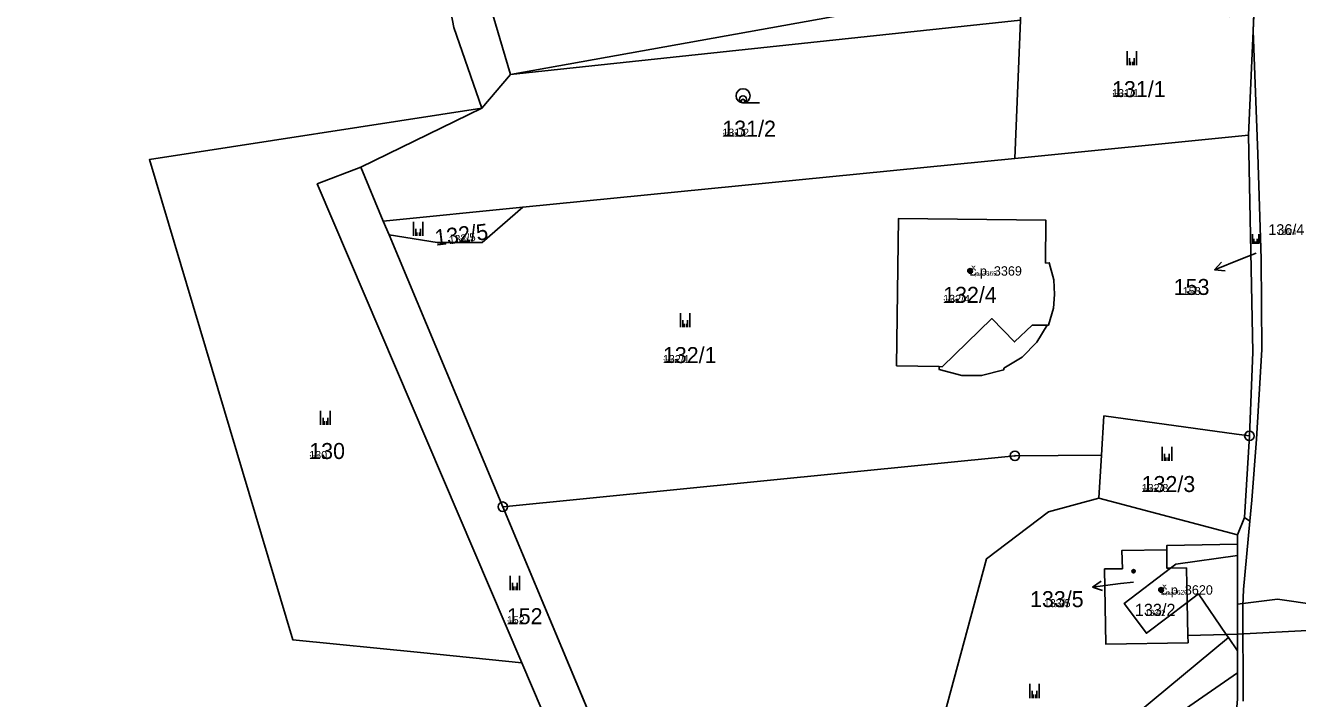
# Model space of a CAD drawing. Extents: x -759873 to -758487, y -975024 to -973516.
# Drawn here: x -759433 to -759297.9, y -974475 to -974403.4 of the extents above; entities that cross this region are included whole.
import ezdxf

# ---------------------------------------------------------------- set-up
doc = ezdxf.new("R2010")
doc.units = 0
for name, color, linetype in [('KAT_02_hranice parcel', 7, 'Continuous'), ('KAT_03_1000_st čísla parcelní', 7, 'Continuous'), ('KAT_03_1000_čísla parcelní', 7, 'Continuous'), ('KAT_03_1000_čísla popisná', 7, 'Continuous'), ('KAT_03_250_st čísla parcelní', 7, 'Continuous'), ('KAT_03_250_čísla parcelní', 7, 'Continuous'), ('KAT_03_250_čísla popisná', 7, 'Continuous'), ('KAT_03_500_st čísla parcelní', 7, 'Continuous'), ('KAT_03_500_čísla parcelní', 7, 'Continuous'), ('KAT_03_500_čísla popisná', 7, 'Continuous'), ('KAT_04_vnitřní kresba', 7, 'Continuous'), ('KAT_05_1000_značky kultur', 7, 'Continuous'), ('KAT_05_250_značky kultur', 7, 'Continuous'), ('KAT_05_500_značky kultur', 7, 'Continuous'), ('KAT_07_1000_značky budov', 7, 'Continuous'), ('KAT_07_250_značky budov', 7, 'Continuous'), ('KAT_07_500_značky budov', 7, 'Continuous'), ('KAT_10_věcná břemena', 7, 'Continuous'), ('KAT_11_značky bodu BP', 7, 'Continuous'), ('KAT_12_pomocná šipka', 7, 'Continuous'), ('KAT_14_plocha_budovy', 7, 'Continuous'), ('KAT_14_plocha_pozemek', 7, 'Continuous')]:
    doc.layers.add(name, color=color, linetype=linetype)

msp = doc.modelspace()

# ---------------------------------------------------------------- linework, layer by layer
at = {"layer": 'KAT_02_hranice parcel'}
for p, q in [((-759302.67, -974403.97), (-759302.28, -974395.1)), ((-759303.15, -974415.06), (-759302.67, -974403.97)), ((-759397.43, -974418.48), (-759384.57, -974412.22)), ((-759327.97, -974417.54), (-759303.15, -974415.06)), ((-759380.23, -974422.73), (-759327.97, -974417.54)), ((-759397.43, -974418.48), (-759395.04, -974424.2)), ((-759395.04, -974424.2), (-759380.23, -974422.73)), ((-759394.43, -974425.67), (-759395.04, -974424.2)), ((-759394.43, -974425.67), (-759382.35, -974454.57)), ((-759303.57, -974455.73), (-759303.06, -974447.05)), ((-759319.06, -974453.68), (-759318.77, -974449.1)), ((-759319.06, -974453.68), (-759304.32, -974457.57)), ((-759382.35, -974454.57), (-759357.95, -974512.98)), ((-759304.32, -974457.57), (-759303.57, -974455.73)), ((-759304.32, -974458.57), (-759304.32, -974457.57)), ((-759304.32, -974458.57), (-759304.32, -974459.77)), ((-759305.51, -974468.16), (-759305.29, -974468.48)), ((-759304.33, -974469.88), (-759305.29, -974468.48)), ((-759304.32, -974472.23), (-759304.33, -974469.88)), ((-759304.33, -974475.03), (-759304.32, -974472.23))]:
    msp.add_line(p, q, dxfattribs=at)
for points in [[(-759387.93, -974386.9), (-759390.61, -974387.43), (-759387.55, -974403.62), (-759384.57, -974412.22)], [(-759384.57, -974412.22), (-759381.52, -974408.61), (-759327.22, -974398.86)], [(-759327.22, -974398.86), (-759327.38, -974402.84), (-759327.97, -974417.54)], [(-759303.57, -974455.73), (-759303.02, -974456.1), (-759302.81, -974453.88), (-759302.31, -974447.39), (-759301.72, -974437.86), (-759301.82, -974428.21), (-759302.16, -974417.11), (-759302.67, -974403.97)], [(-759384.57, -974412.22), (-759419.87, -974417.67), (-759404.65, -974468.71), (-759391.07, -974470.08), (-759380.34, -974471.16)], [(-759303.06, -974447.05), (-759302.68, -974438.14), (-759303.15, -974415.06)], [(-759380.34, -974471.16), (-759402.05, -974420.26), (-759397.43, -974418.48)], [(-759380.23, -974422.73), (-759384.54, -974426.48), (-759389.3, -974426.48), (-759394.43, -974425.67)], [(-759323.74, -974432), (-759323.86, -974433.48), (-759324.38, -974435.26), (-759324.55, -974435.26), (-759325.63, -974437.07), (-759327.19, -974438.69), (-759329.14, -974439.85), (-759329.14, -974440.03), (-759331.5, -974440.64), (-759333.61, -974440.62), (-759335.99, -974439.99), (-759336.02, -974439.68), (-759340.53, -974439.58), (-759340.31, -974423.92), (-759324.67, -974424.12), (-759324.7, -974428.67), (-759324.32, -974428.64), (-759323.81, -974430.46), (-759323.74, -974432)], [(-759318.77, -974449.1), (-759318.5, -974444.92), (-759304.42, -974446.86), (-759303.06, -974447.05)], [(-759382.35, -974454.57), (-759327.96, -974449.16), (-759318.77, -974449.1)], [(-759336.77, -974481.63), (-759330.97, -974460.1), (-759324.39, -974455.12), (-759319.06, -974453.68)], [(-759305.51, -974468.16), (-759309.59, -974468.25), (-759309.57, -974469.03), (-759318.32, -974469.18), (-759318.44, -974461.19), (-759316.55, -974461.17), (-759316.6, -974459.22), (-759311.84, -974459.15), (-759311.84, -974458.71), (-759304.32, -974458.57)], [(-759304.32, -974459.77), (-759310.86, -974460.68), (-759311.42, -974461.1), (-759316.34, -974464.86), (-759314, -974468.02), (-759309.67, -974464.75), (-759308.47, -974463.85), (-759305.51, -974468.16)], [(-759304.33, -974469.88), (-759304.33, -974468.13), (-759304.32, -974459.77)], [(-759305.29, -974468.48), (-759324.8, -974484.72), (-759336.77, -974481.63)], [(-759380.34, -974471.16), (-759364.28, -974508.82), (-759352.33, -974538.42), (-759351.8, -974547.79)], [(-759317.94, -974495.22), (-759325.13, -974486.64), (-759304.32, -974472.23)]]:
    msp.add_lwpolyline(points, dxfattribs=at)
at = {"layer": 'KAT_03_1000_čísla popisná'}
for centre in [(-759332.72, -974429.51), (-759312.44, -974463.42)]:
    msp.add_circle(centre, 0.25, dxfattribs=at)
at = {"layer": 'KAT_03_250_čísla popisná'}
for centre in [(-759332.72, -974429.51), (-759312.44, -974463.42)]:
    msp.add_circle(centre, 0.0625, dxfattribs=at)
at = {"layer": 'KAT_03_500_čísla popisná'}
for centre in [(-759332.72, -974429.51), (-759312.44, -974463.42)]:
    msp.add_circle(centre, 0.125, dxfattribs=at)
at = {"layer": 'KAT_04_vnitřní kresba'}
for p, q in [((-759387.93, -974386.9), (-759381.52, -974408.61)), ((-759381.52, -974408.61), (-759327.38, -974402.84)), ((-759335.69, -974439.69), (-759330.4, -974434.57)), ((-759330.4, -974434.57), (-759327.99, -974437.06)), ((-759327.99, -974437.06), (-759326.12, -974435.27)), ((-759326.12, -974435.27), (-759324.55, -974435.26)), ((-759336.02, -974439.68), (-759335.69, -974439.69)), ((-759303.69, -974463.38), (-759303.02, -974456.1)), ((-759311.84, -974459.15), (-759311.82, -974461.11)), ((-759311.82, -974461.11), (-759311.42, -974461.1)), ((-759311.42, -974461.1), (-759309.75, -974461.08)), ((-759309.75, -974461.08), (-759309.67, -974464.75)), ((-759303.76, -974465.1), (-759303.69, -974463.38)), ((-759309.67, -974464.75), (-759309.59, -974468.25)), ((-759303.76, -974465.1), (-759303.71, -974475.23)), ((-759305.51, -974468.16), (-759304.33, -974468.13))]:
    msp.add_line(p, q, dxfattribs=at)
at = {"layer": 'KAT_05_1000_značky kultur'}
for p, q in [((-759316.05, -974407.63), (-759316.05, -974406.13)), ((-759315.05, -974407.63), (-759315.05, -974406.13)), ((-759356.83, -974411.64), (-759355.08, -974411.64)), ((-759391.84, -974425.79), (-759391.84, -974424.29)), ((-759390.84, -974425.79), (-759390.84, -974424.29)), ((-759302.74, -974426.61), (-759302.74, -974425.6)), ((-759302.07, -974426.61), (-759302.07, -974425.6)), ((-759363.48, -974435.5), (-759363.48, -974434)), ((-759362.48, -974435.5), (-759362.48, -974434)), ((-759401.69, -974445.87), (-759401.69, -974444.37)), ((-759400.69, -974445.87), (-759400.69, -974444.37)), ((-759312.31, -974449.7), (-759312.31, -974448.2)), ((-759311.31, -974449.7), (-759311.31, -974448.2)), ((-759381.57, -974463.43), (-759381.57, -974461.93)), ((-759380.57, -974463.43), (-759380.57, -974461.93)), ((-759326.38, -974474.91), (-759326.38, -974473.41)), ((-759325.38, -974474.91), (-759325.38, -974473.41))]:
    msp.add_line(p, q, dxfattribs=at)
msp.add_circle((-759356.83, -974410.89), 0.75, dxfattribs=at)
at = {"layer": 'KAT_05_250_značky kultur'}
for p, q in [((-759315.67, -974407.63), (-759315.67, -974407.26)), ((-759315.42, -974407.63), (-759315.42, -974407.26)), ((-759356.84, -974411.64), (-759356.4, -974411.64)), ((-759391.46, -974425.79), (-759391.46, -974425.42)), ((-759391.21, -974425.79), (-759391.21, -974425.42)), ((-759302.49, -974426.61), (-759302.49, -974426.36)), ((-759302.32, -974426.61), (-759302.32, -974426.36)), ((-759363.1, -974435.5), (-759363.1, -974435.12)), ((-759362.85, -974435.5), (-759362.85, -974435.12)), ((-759401.31, -974445.87), (-759401.31, -974445.49)), ((-759401.06, -974445.87), (-759401.06, -974445.49)), ((-759311.93, -974449.7), (-759311.93, -974449.33)), ((-759311.68, -974449.7), (-759311.68, -974449.33)), ((-759381.19, -974463.43), (-759381.19, -974463.06)), ((-759380.94, -974463.43), (-759380.94, -974463.06)), ((-759326, -974474.91), (-759326, -974474.54)), ((-759325.75, -974474.91), (-759325.75, -974474.54))]:
    msp.add_line(p, q, dxfattribs=at)
msp.add_circle((-759356.84, -974411.45), 0.187, dxfattribs=at)
at = {"layer": 'KAT_05_500_značky kultur'}
for p, q in [((-759315.8, -974407.63), (-759315.8, -974406.88)), ((-759315.3, -974407.63), (-759315.3, -974406.88)), ((-759356.84, -974411.64), (-759355.96, -974411.64)), ((-759391.59, -974425.79), (-759391.59, -974425.04)), ((-759391.08, -974425.79), (-759391.08, -974425.04)), ((-759302.57, -974426.61), (-759302.57, -974426.11)), ((-759302.24, -974426.61), (-759302.24, -974426.11)), ((-759363.23, -974435.5), (-759363.23, -974434.75)), ((-759362.72, -974435.5), (-759362.72, -974434.75)), ((-759401.44, -974445.87), (-759401.44, -974445.12)), ((-759400.94, -974445.87), (-759400.94, -974445.12)), ((-759312.06, -974449.7), (-759312.06, -974448.95)), ((-759311.56, -974449.7), (-759311.56, -974448.95)), ((-759381.32, -974463.43), (-759381.32, -974462.68)), ((-759380.82, -974463.43), (-759380.82, -974462.68)), ((-759326.13, -974474.91), (-759326.13, -974474.16)), ((-759325.62, -974474.91), (-759325.62, -974474.16))]:
    msp.add_line(p, q, dxfattribs=at)
msp.add_circle((-759356.84, -974411.26), 0.375, dxfattribs=at)
at = {"layer": 'KAT_07_1000_značky budov'}
for centre in [(-759332.73, -974429.51), (-759315.36, -974461.43), (-759312.45, -974463.42)]:
    msp.add_circle(centre, 0.175, dxfattribs=at)
at = {"layer": 'KAT_07_250_značky budov'}
for centre in [(-759332.72, -974429.51), (-759315.35, -974461.43), (-759312.44, -974463.42)]:
    msp.add_circle(centre, 0.0437, dxfattribs=at)
at = {"layer": 'KAT_07_500_značky budov'}
for centre in [(-759332.72, -974429.51), (-759315.35, -974461.43), (-759312.44, -974463.42)]:
    msp.add_circle(centre, 0.0875, dxfattribs=at)
at = {"layer": 'KAT_10_věcná břemena'}
msp.add_lwpolyline([(-759304.33, -974464.94), (-759304.33, -974468.13), (-759296.23, -974467.68), (-759296.02, -974466.22), (-759295.88, -974464.99), (-759300.06, -974464.4)], close=True, dxfattribs=at)
at = {"layer": 'KAT_11_značky bodu BP'}
for centre, radius in [((-759303.06, -974447.05), 0.5), ((-759303.06, -974447.05), 0.0303), ((-759327.96, -974449.16), 0.5), ((-759327.96, -974449.16), 0.0303), ((-759382.35, -974454.57), 0.5), ((-759382.35, -974454.57), 0.0303)]:
    msp.add_circle(centre, radius, dxfattribs=at)
at = {"layer": 'KAT_12_pomocná šipka'}
for p, q in [((-759303.97, -974428.27), (-759306.75, -974429.39)), ((-759306.75, -974429.39), (-759306.01, -974428.56)), ((-759302.34, -974427.61), (-759303.97, -974428.27)), ((-759306.75, -974429.39), (-759305.64, -974429.48)), ((-759319.72, -974463.12), (-759318.79, -974462.5)), ((-759316.74, -974462.75), (-759319.72, -974463.12)), ((-759319.72, -974463.12), (-759318.66, -974463.49)), ((-759315.35, -974462.59), (-759316.74, -974462.75))]:
    msp.add_line(p, q, dxfattribs=at)
at = {"layer": 'KAT_14_plocha_budovy'}
for points in [[(-759340.53, -974439.58), (-759336.02, -974439.68), (-759335.69, -974439.69), (-759330.4, -974434.57), (-759327.99, -974437.06), (-759326.12, -974435.27), (-759324.55, -974435.26), (-759324.38, -974435.26), (-759323.86, -974433.48), (-759323.74, -974432), (-759323.81, -974430.46), (-759324.32, -974428.64), (-759324.7, -974428.67), (-759324.67, -974424.12), (-759340.31, -974423.92)], [(-759316.6, -974459.22), (-759316.55, -974461.17), (-759318.44, -974461.19), (-759318.32, -974469.18), (-759309.57, -974469.03), (-759309.59, -974468.25), (-759309.67, -974464.75), (-759309.75, -974461.08), (-759311.42, -974461.1), (-759311.82, -974461.11), (-759311.84, -974459.15)]]:
    msp.add_lwpolyline(points, close=True, dxfattribs=at)
at = {"layer": 'KAT_14_plocha_pozemek'}
for points in [[(-759364.28, -974508.82), (-759380.34, -974471.16), (-759391.07, -974470.08), (-759404.65, -974468.71), (-759419.87, -974417.67), (-759384.57, -974412.22), (-759387.55, -974403.62), (-759390.61, -974387.43), (-759387.93, -974386.9), (-759391.56, -974372.71), (-759395.68, -974347.5), (-759404.28, -974320.35), (-759405.51, -974318.2), (-759448.08, -974345.12), (-759474.9, -974360.23), (-759479.3, -974362.15), (-759507.25, -974381.64), (-759510.36, -974386.54), (-759513.7, -974388.36), (-759504.64, -974393.1), (-759481.61, -974430.04), (-759469.74, -974487.16)], [(-759301.15, -974335.03), (-759300.63, -974337.72), (-759299.79, -974343.91), (-759299.65, -974345.36), (-759299.06, -974360.01), (-759300.3, -974375.32), (-759301.72, -974375.45), (-759301.51, -974379.07), (-759301.68, -974382.67), (-759302.28, -974395.1), (-759302.67, -974403.97), (-759302.16, -974417.11), (-759301.82, -974428.21), (-759301.72, -974437.86), (-759302.31, -974447.39), (-759302.81, -974453.88)], [(-759302.81, -974453.88), (-759303.02, -974456.1), (-759303.57, -974455.73), (-759304.32, -974457.57), (-759304.32, -974458.57), (-759304.32, -974459.77)], [(-759304.32, -974459.77), (-759304.33, -974468.13), (-759304.33, -974469.88), (-759304.32, -974472.23), (-759304.33, -974475.03)]]:
    msp.add_lwpolyline(points, dxfattribs=at)
for points in [[(-759327.22, -974398.86), (-759326.51, -974381.38), (-759360.24, -974383.98), (-759369.6, -974385.4), (-759387.93, -974386.9), (-759390.61, -974387.43), (-759387.55, -974403.62), (-759384.57, -974412.22), (-759381.52, -974408.61)], [(-759302.28, -974395.1), (-759305.13, -974395.51), (-759305.17, -974402.44), (-759314.51, -974402.42), (-759314.48, -974396.74), (-759318, -974397.2), (-759327.22, -974398.86), (-759327.38, -974402.84), (-759327.97, -974417.54), (-759303.15, -974415.06), (-759302.67, -974403.97)], [(-759380.23, -974422.73), (-759327.97, -974417.54), (-759327.38, -974402.84), (-759327.22, -974398.86), (-759381.52, -974408.61), (-759384.57, -974412.22), (-759397.43, -974418.48), (-759395.04, -974424.2)], [(-759302.81, -974453.88), (-759302.31, -974447.39), (-759301.72, -974437.86), (-759301.82, -974428.21), (-759302.16, -974417.11), (-759302.67, -974403.97), (-759303.15, -974415.06), (-759302.68, -974438.14), (-759303.06, -974447.05), (-759303.57, -974455.73), (-759303.02, -974456.1)], [(-759391.07, -974470.08), (-759380.34, -974471.16), (-759402.05, -974420.26), (-759397.43, -974418.48), (-759384.57, -974412.22), (-759419.87, -974417.67), (-759404.65, -974468.71)], [(-759394.43, -974425.67), (-759382.35, -974454.57), (-759327.96, -974449.16), (-759318.77, -974449.1), (-759318.5, -974444.92), (-759304.42, -974446.86), (-759303.06, -974447.05), (-759302.68, -974438.14), (-759303.15, -974415.06), (-759327.97, -974417.54), (-759380.23, -974422.73), (-759384.54, -974426.48), (-759389.3, -974426.48)], [(-759394.43, -974425.67), (-759395.04, -974424.2), (-759397.43, -974418.48), (-759402.05, -974420.26), (-759380.34, -974471.16), (-759364.28, -974508.82), (-759352.33, -974538.42), (-759351.8, -974547.79), (-759346.97, -974548.23), (-759348.95, -974539.45), (-759350.06, -974534.56), (-759357.95, -974512.98), (-759382.35, -974454.57)], [(-759380.23, -974422.73), (-759395.04, -974424.2), (-759394.43, -974425.67), (-759389.3, -974426.48), (-759384.54, -974426.48)], [(-759323.74, -974432), (-759323.86, -974433.48), (-759324.38, -974435.26), (-759324.55, -974435.26), (-759325.63, -974437.07), (-759327.19, -974438.69), (-759329.14, -974439.85), (-759329.14, -974440.03), (-759331.5, -974440.64), (-759333.61, -974440.62), (-759335.99, -974439.99), (-759336.02, -974439.68), (-759340.53, -974439.58), (-759340.31, -974423.92), (-759324.67, -974424.12), (-759324.7, -974428.67), (-759324.32, -974428.64), (-759323.81, -974430.46)], [(-759323.74, -974432), (-759323.81, -974430.46), (-759324.32, -974428.64), (-759324.7, -974428.67), (-759324.67, -974424.12), (-759340.31, -974423.92), (-759340.53, -974439.58), (-759336.02, -974439.68), (-759335.99, -974439.99), (-759333.61, -974440.62), (-759331.5, -974440.64), (-759329.14, -974440.03), (-759329.14, -974439.85), (-759327.19, -974438.69), (-759325.63, -974437.07), (-759324.55, -974435.26), (-759324.38, -974435.26), (-759323.86, -974433.48)], [(-759303.57, -974455.73), (-759303.06, -974447.05), (-759304.42, -974446.86), (-759318.5, -974444.92), (-759318.77, -974449.1), (-759319.06, -974453.68), (-759304.32, -974457.57)], [(-759330.97, -974460.1), (-759324.39, -974455.12), (-759319.06, -974453.68), (-759318.77, -974449.1), (-759327.96, -974449.16), (-759382.35, -974454.57), (-759357.95, -974512.98), (-759344.1, -974504.48), (-759340.97, -974501.58), (-759338.54, -974498.57), (-759336.77, -974489.92), (-759336.77, -974481.63)], [(-759309.59, -974468.25), (-759309.57, -974469.03), (-759318.32, -974469.18), (-759318.44, -974461.19), (-759316.55, -974461.17), (-759316.6, -974459.22), (-759311.84, -974459.15), (-759311.84, -974458.71), (-759304.32, -974458.57), (-759304.32, -974457.57), (-759319.06, -974453.68), (-759324.39, -974455.12), (-759330.97, -974460.1), (-759336.77, -974481.63), (-759324.8, -974484.72), (-759305.29, -974468.48), (-759305.51, -974468.16)], [(-759305.51, -974468.16), (-759308.47, -974463.85), (-759309.67, -974464.75), (-759314, -974468.02), (-759316.34, -974464.86), (-759311.42, -974461.1), (-759310.86, -974460.68), (-759304.32, -974459.77), (-759304.32, -974458.57), (-759311.84, -974458.71), (-759311.84, -974459.15), (-759316.6, -974459.22), (-759316.55, -974461.17), (-759318.44, -974461.19), (-759318.32, -974469.18), (-759309.57, -974469.03), (-759309.59, -974468.25)], [(-759314, -974468.02), (-759309.67, -974464.75), (-759308.47, -974463.85), (-759305.51, -974468.16), (-759305.29, -974468.48), (-759304.33, -974469.88), (-759304.33, -974468.13), (-759304.32, -974459.77), (-759310.86, -974460.68), (-759311.42, -974461.1), (-759316.34, -974464.86)], [(-759330.9, -974496.56), (-759328.49, -974490.85), (-759322.44, -974493.37), (-759317.94, -974495.22), (-759325.13, -974486.64), (-759304.32, -974472.23), (-759304.33, -974469.88), (-759305.29, -974468.48), (-759324.8, -974484.72), (-759336.77, -974481.63), (-759336.77, -974489.92), (-759338.54, -974498.57), (-759325.96, -974501.3), (-759325.12, -974499.4), (-759325.58, -974499.18), (-759325.42, -974498.8)], [(-759305.19, -974485.49), (-759304.33, -974475.03), (-759304.32, -974472.23), (-759325.13, -974486.64), (-759317.94, -974495.22), (-759309.83, -974496.47)]]:
    msp.add_lwpolyline(points, close=True, dxfattribs=at)

# ---------------------------------------------------------------- texts
at = {"layer": 'KAT_03_1000_st čísla parcelní'}
for s, height, p in [('132/4', 1.7, (-759335.58, -974432.9)), ('133/5', 1.7, (-759326.35, -974465.25)), ('133/2', 1.288, (-759315.22, -974466.18))]:
    msp.add_text(s, height=height, dxfattribs=at).set_placement(p)
at = {"layer": 'KAT_03_1000_čísla parcelní'}
for s, height, p in [('131/1', 1.7, (-759317.64, -974411.03)), ('131/2', 1.7, (-759359.03, -974415.23)), ('136/4', 1.139, (-759301.04, -974425.68)), ('153', 1.7, (-759311.09, -974432.06)), ('132/1', 1.7, (-759365.34, -974439.3)), ('130', 1.7, (-759402.9, -974449.5)), ('132/3', 1.7, (-759314.5, -974453.01)), ('152', 1.7, (-759381.92, -974467.06))]:
    msp.add_text(s, height=height, dxfattribs=at).set_placement(p)
msp.add_text('132/5', height=1.7, rotation=7, dxfattribs=at).set_placement((-759389.47, -974426.83))
at = {"layer": 'KAT_03_1000_čísla popisná'}
for s, p in [('č.p. 3369', (-759332.72, -974430.01)), ('č.p. 3620', (-759312.44, -974463.92))]:
    msp.add_text(s, height=1, dxfattribs=at).set_placement(p)
at = {"layer": 'KAT_03_250_st čísla parcelní'}
for s, height, p in [('132/4', 0.425, (-759335.58, -974432.9)), ('133/5', 0.425, (-759324.16, -974465.25)), ('133/2', 0.322, (-759313.57, -974466.18))]:
    msp.add_text(s, height=height, dxfattribs=at).set_placement(p)
at = {"layer": 'KAT_03_250_čísla parcelní'}
for s, height, p in [('131/1', 0.425, (-759317.64, -974411.03)), ('131/2', 0.425, (-759359.03, -974415.23)), ('136/4', 0.285, (-759299.57, -974425.68)), ('153', 0.425, (-759309.65, -974432.06)), ('132/1', 0.425, (-759365.34, -974439.3)), ('130', 0.425, (-759402.9, -974449.5)), ('132/3', 0.425, (-759314.5, -974453.01)), ('152', 0.425, (-759381.92, -974467.06))]:
    msp.add_text(s, height=height, dxfattribs=at).set_placement(p)
msp.add_text('132/5', height=0.425, rotation=7, dxfattribs=at).set_placement((-759387.29, -974426.56))
at = {"layer": 'KAT_03_250_čísla popisná'}
for s, p in [('č.p. 3369', (-759332.72, -974430.01)), ('č.p. 3620', (-759312.44, -974463.92))]:
    msp.add_text(s, height=0.25, dxfattribs=at).set_placement(p)
at = {"layer": 'KAT_03_500_st čísla parcelní'}
for s, height, p in [('132/4', 0.85, (-759335.58, -974432.9)), ('133/5', 0.85, (-759324.89, -974465.25)), ('133/2', 0.644, (-759314.12, -974466.18))]:
    msp.add_text(s, height=height, dxfattribs=at).set_placement(p)
at = {"layer": 'KAT_03_500_čísla parcelní'}
for s, height, p in [('131/1', 0.85, (-759317.64, -974411.03)), ('131/2', 0.85, (-759359.03, -974415.23)), ('136/4', 0.569, (-759300.06, -974425.68)), ('153', 0.85, (-759310.13, -974432.06)), ('132/1', 0.85, (-759365.34, -974439.3)), ('130', 0.85, (-759402.9, -974449.5)), ('132/3', 0.85, (-759314.5, -974453.01)), ('152', 0.85, (-759381.92, -974467.06))]:
    msp.add_text(s, height=height, dxfattribs=at).set_placement(p)
msp.add_text('132/5', height=0.85, rotation=7, dxfattribs=at).set_placement((-759388.02, -974426.65))
at = {"layer": 'KAT_03_500_čísla popisná'}
for s, p in [('č.p. 3369', (-759332.72, -974430.01)), ('č.p. 3620', (-759312.44, -974463.92))]:
    msp.add_text(s, height=0.5, dxfattribs=at).set_placement(p)

doc.saveas('drawing.dxf')
